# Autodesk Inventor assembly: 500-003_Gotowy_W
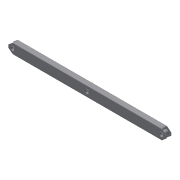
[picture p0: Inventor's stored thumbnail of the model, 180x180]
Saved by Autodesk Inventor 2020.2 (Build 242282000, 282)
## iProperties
Created: 2016-09
Part Number: 500-003_Gotowy_W
Document SubType Name: Assembly
Designer: F.Stasiak
Description: Ramię pojedyncze
Manager: www.cadconsulting.pl
Company: Fabian Stasiak CAD Consulting
Author: F.Stasiak
Subject: Zbiór ćwiczeń. Autodesk Inventor 2020. Kurs podstawowy
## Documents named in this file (3)
- C:\2020_Kurs_podstawowy\R6 Zespoły\Warsztat\Komponenty\500-003_Gotowy_W.iam
- C:\2020_Kurs_podstawowy\R6 Zespoły\Warsztat\Komponenty\DIN 59 410 - 500-04-01.ipt
- C:\2020_Kurs_podstawowy\R6 Zespoły\Warsztat\Komponenty\500-03-02.ipt
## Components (4 placed, 2 different names)
1. DIN 59 410 - 500-04-01:1 — Kąt:1, Zestawiający:6
2. 500-03-02:1
3. 500-03-02:2 — Zestawiający:5
4. 500-03-02:3
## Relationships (3: Mate 2, Angle 1)
- Zestawiający:5 [Mate]: 500-03-02:2
- Kąt:1 [Angle]: DIN 59 410 - 500-04-01:1
- Zestawiający:6 [Mate]: DIN 59 410 - 500-04-01:1
